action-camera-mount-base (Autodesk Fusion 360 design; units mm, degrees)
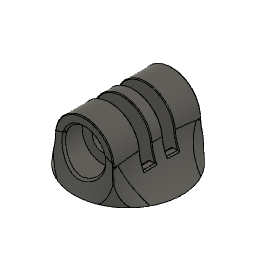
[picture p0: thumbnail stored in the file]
sketch "Sketch2" plane through (0, 0, 0) normal (1, 0, 0) x axis (0, 0, -1)
  line L1 (0, 60) -> (0, 0)
  line L2 (-14.75, 60) -> (0, 60)
  line L3 (-12.2, 0) -> (0, 0)
  line L4 (-12.2, 0) -> (-14.75, 60)
  point P1 (0, 0)
  point P2 (0, 0)
  point P5 (0, 0)
  point P3 (0, 60)
  point P6 (-12.2, 0)
  point P4 (-14.75, 60)
  coincident P1 P2
  vertical L1
  perpendicular L1 L2
  coincident P1 P5
  perpendicular L1 L3
  dimension "d4" distance P2 P3 = 60
  dimension "d7" distance P5 P6 = 12.2
  dimension "d8" distance P3 P4 = 14.75
revolve "Revolve1" sketch "Sketch2" AlongAngle 360
extrude "Extrude2" add of existing geometry blind 5
sketch "Sketch3" plane through (0, 0, 0) normal (1, 0, 0) x axis (0, 0, -1)
mesh "Mesh1"
extrude "Extrude3" add of existing geometry blind 1.394
chamfer "Chamfer1" distance 2.905
extrude "Extrude4" add of existing geometry blind 1.362
sketch "Sketch4" plane through (0, 0, 0) normal (1, 0, 0) x axis (0, 0, -1)
  line L1 (8, 77) -> (8, 67)
  line L2 (-8, 67) -> (-8, 77)
  line L3 (8, 67) -> (-8, 67)
  arc A1 centre (0, 77) radius 8 clockwise from (-8, 77) to (8, 77)
  circle C1 centre (0, 77) radius 2.75
  vertical L1
  vertical L2
  tangent L2 A1
  concentric A1 C1
  perpendicular L1 L3
  dimension "d18" diameter C1 = 5.5
extrude "Extrude5" new body sketch "Sketch4" along normal blind 8
extrude "Extrude6" cut of existing geometry blind -5
extrude "Extrude7" new body sketch "Sketch4" against normal blind 1.58
extrude "Extrude8" add sketch "Sketch4" along normal blind 1.58
extrude "Extrude9" add of existing geometry blind 17
extrude "Extrude10" add of existing geometry blind 0.18
extrude "Extrude11" cut of existing geometry blind -0.01
extrude "Extrude12" cut of existing geometry blind -0.01
move_face "MoveFace1"
extrude "Extrude13" add of existing geometry blind 6.41
extrude "Extrude14" cut of existing geometry blind -6.41
extrude "Extrude15" add sketch "Sketch4" against normal blind 1.58
extrude "Extrude16" add sketch "Sketch4" along normal blind 1.58
delete_face "DeleteFace1"
sketch "Sketch5" plane through (7.99, 0, 0) normal (1, 0, 0) x axis (0, 0, -1)
  line L1 (8, 67.756) -> (-8, 67.756)
  line L2 (8, 77) -> (8, 67.756)
  line L3 (-8, 67.756) -> (-8, 77)
  line L4 (0, 81.6188) -> (4, 79.3094)
  line L5 (-4, 79.3094) -> (0, 81.6188)
  line L6 (-4, 74.6906) -> (-4, 79.3094)
  line L7 (0, 72.3812) -> (-4, 74.6906)
  line L8 (4, 74.6906) -> (0, 72.3812)
  line L9 (4, 79.3094) -> (4, 74.6906)
  line L10 (-8, 69.1448) -> (-8, 77)
  line L11 (8, 69.1448) -> (-8, 69.1448)
  line L12 (8, 77) -> (8, 69.1448)
  arc A1 centre (0, 77) radius 8 clockwise from (-8, 77) to (8, 77)
  circle C1 centre (0, 77) radius 2.75
  arc A2 centre (0, 77) radius 8 clockwise from (-8, 77) to (8, 77)
  point P6 (0, 77)
  point P13 (0, 77)
  point P5 (-8, 77)
  point P18 (-8, 77)
  coincident P6 P13
  parallel L9 L10
  perpendicular L10 L11
  perpendicular L11 L12
  tangent L12 A2
  coincident P5 P18
extrude "Extrude17" add sketch "Sketch5" profile of L2 A1 L3 L4 L5 L6 L7 L8 L9 L10 L11 L12 along normal blind 4
extrude "Extrude18" add of existing geometry blind 2
chamfer "Chamfer2" distance 0.5
chamfer "Chamfer3" distance 2.75
fillet "Fillet1" radius 9
sketch "Sketch6" plane through (-7.99, 0, 0) normal (-1, 0, 0) x axis (0, 0, 1)
  line L1 (8, 67.756) -> (-8, 67.756)
  line L2 (8, 77) -> (8, 67.756)
  line L3 (-8, 67.756) -> (-8, 77)
  arc A1 centre (0, 77) radius 8 clockwise from (-8, 77) to (8, 77)
  circle C1 centre (0, 77) radius 2.75
  circle C2 centre (0, 77) radius 5.5
  concentric A1 C2
  dimension "d51" diameter C2 = 11
extrude "Extrude19" add sketch "Sketch6" profile of L1 L2 A1 L3 C2 along normal blind 4
chamfer "Chamfer4" distance 0.5
chamfer "Chamfer5" distance 2.7
fillet "Fillet2" radius 9
fillet "Fillet3" radius 9.5
fillet "Fillet4" radius 9.5
sketch "Sketch7" plane through (0, 0, 0) normal (0, 1, 0) x axis (1, 0, 0)
  circle C1 centre (0, 0) radius 15.5242
  point P1 (0, 0)
  point P2 (0, 0)
  coincident P1 P2
revolve "Revolve2" sketch "Sketch2" AlongAngle 360
extrude "Extrude21" add of existing geometry blind 7
extrude "Extrude22" add of existing geometry blind 1
extrude "Extrude23" add sketch "Sketch4" along normal blind 12
extrude "Extrude24" add sketch "Sketch4" against normal blind 12
fillet "Fillet5" radius 26
fillet "Fillet6" radius 26
fillet "Fillet7" radius 12
fillet "Fillet8" radius 12
sketch "Sketch8" plane through (-12, 0, 0) normal (-1, 0, 0) x axis (0, 0, 1)
  curve K1 (-7.9579, 77.8197) -> (-0.8377, 79.6193)
  curve K2 (0.8377, 79.6193) -> (7.9579, 77.8197)
  line L1 (0, 81.6188) -> (4, 79.3094)
  line L2 (-4, 79.3094) -> (0, 81.6188)
  line L3 (-4, 74.6906) -> (-4, 79.3094)
  line L4 (0, 72.3812) -> (-4, 74.6906)
  line L5 (4, 74.6906) -> (0, 72.3812)
  line L6 (4, 79.3094) -> (4, 74.6906)
  arc A1 centre (0, 77) radius 2.75 clockwise from (-0.8377, 79.6193) to (0.8377, 79.6193)
  arc A2 centre (0, 77) radius 8 clockwise from (-7.9579, 77.8197) to (7.9579, 77.8197)
  point P5 (0, 77)
  point P13 (0, 77)
  coincident P5 P13
extrude "Extrude25" cut sketch "Sketch8" profile of K1 A1 K2 L1 L2 L3 L4 L5 L6 along normal blind 3
extrude "Extrude26" cut sketch "Sketch8" profile of K1 A1 K2 L1 L2 L3 L4 L5 L6 against normal blind 4
chamfer "Chamfer6" distance 0.5
sketch "Sketch9" plane through (12, 0, 0) normal (1, 0, 0) x axis (0, 0, -1)
  curve K1 (-7.9579, 77.8197) -> (-0.8377, 79.6193)
  curve K2 (0.8377, 79.6193) -> (7.9579, 77.8197)
  arc A1 centre (0, 77) radius 2.75 clockwise from (-0.8377, 79.6193) to (0.8377, 79.6193)
  arc A2 centre (0, 77) radius 8 clockwise from (-7.9579, 77.8197) to (7.9579, 77.8197)
  circle C1 centre (0, 77) radius 5.5
  concentric A1 C1
  dimension "d86" diameter C1 = 11
extrude "Extrude27" cut sketch "Sketch9" profile of K1 A1 K2 C1 along normal blind 2
extrude "Extrude28" cut sketch "Sketch9" profile of K1 A1 K2 C1 against normal blind 4
chamfer "Chamfer7" distance 0.5
sketch "Sketch10" plane through (0, 0, 0) normal (0, 0, 1) x axis (1, 0, 0)
  line L1 (-1.58, 86) -> (0, 86)
  line L2 (-4.83, 86) -> (-1.58, 86)
  line L3 (1.58, 86) -> (0, 86)
  line L4 (4.83, 86) -> (1.58, 86)
  line L5 (7.99, 86) -> (4.83, 86)
  line L6 (-7.99, 86) -> (-4.83, 86)
  line L7 (1.58, 85) -> (4.83, 85)
  line L8 (1.58, 69) -> (1.58, 85)
  line L9 (4.83, 69) -> (1.58, 69)
  line L10 (4.83, 85) -> (4.83, 69)
  line L11 (-4.83, 85) -> (-1.58, 85)
  line L12 (-4.83, 69) -> (-4.83, 85)
  line L13 (-1.58, 69) -> (-4.83, 69)
  line L14 (-1.58, 85) -> (-1.58, 69)
  point P2 (0, 86)
  point P3 (-1.58, 86)
  point P4 (-4.83, 86)
  point P5 (1.58, 86)
  point P6 (4.83, 86)
  point P7 (7.99, 86)
  point P8 (-7.99, 86)
  horizontal L1
  parallel L1 L2
  parallel L1 L3
  parallel L3 L4
  parallel L4 L5
  parallel L2 L6
  horizontal L7
  vertical L8
  horizontal L9
  vertical L10
  horizontal L11
  vertical L12
  horizontal L13
  vertical L14
  dimension "d92" distance P2 P3 = 1.58
  dimension "d93" distance P3 P4 = 3.25
  dimension "d94" distance P2 P5 = 1.58
  dimension "d95" distance P5 P6 = 3.25
  dimension "d96" distance P6 P7 = 3.16
  dimension "d97" distance P4 P8 = 3.16
extrude "Extrude40" new body sketch "Sketch10" profile of L7 L8 L9 L10 L11 L12 L13 L14 along normal blind 8.1
extrude "Extrude41" add of existing geometry blind 8.1
extrude "Extrude42" add of existing geometry blind 0.2
sketch "Sketch14" plane through (-4.83, 0, 0) normal (-1, 0, 0) x axis (0, 0, 1)
  line L1 (-8.1, 76.9) -> (-8.1, 85)
  line L2 (8.1, 85) -> (-8.1, 85)
  line L3 (8.1, 76.9) -> (8.1, 85)
  arc A1 centre (0, 76.9) radius 8.1 clockwise from (8.1, 76.9) to (-8.1, 76.9)
  point P2 (-8.1, 85)
  point P3 (-8.1, 76.9)
  point P4 (8.1, 85)
  point P5 (8.1, 76.9)
  vertical L1
  perpendicular L1 L2
  perpendicular L2 L3
  tangent L1 A1
  dimension "d149" distance P2 P3 = 8.1
  dimension "d151" distance P4 P5 = 8.1
extrude "Extrude43" cut sketch "Sketch14" against normal blind 1
extrude "Extrude44" cut of existing geometry blind -10
extrude "Extrude45" add of existing geometry blind 1
combine "Combine4"
combine "Combine5"
chamfer "Chamfer9" distance 3.5
fillet "Fillet12" radius 0.5
fillet "Fillet13" radius 0.2
copy_paste_bodies "CopyPasteBodies3"
sketch "Sketch15" plane through (0, 0, 0) normal (0, 1, 0) x axis (1, 0, 0)
  circle C1 centre (0, 0) radius 15
  point P1 (0, 0)
  point P2 (0, 0)
  coincident P1 P2
extrude "Extrude46" cut sketch "Sketch15" along normal blind 30
move "Move2"
extrude "Extrude47" cut of existing geometry blind -1
extrude "Extrude48" cut of existing geometry blind -1
copy_paste_bodies "CopyPasteBodies4"
extrude "Extrude49" cut sketch "Sketch15" along normal blind 38
move "Move3"
move_face "MoveFace2"
move_face "MoveFace3"
move_face "MoveFace4"
move_face "MoveFace5"
move_face "MoveFace6"
move_face "MoveFace7"
move_face "MoveFace8"
move "Move4"
fillet "Fillet14" radius 0.2
sketch "Sketch16" plane through (0, 0, 0) normal (0, 1, 0) x axis (1, 0, 0)
  circle C1 centre (0, 0) radius 2.5
  point P1 (0, 0)
  point P2 (0, 0)
  coincident P1 P2
align "Align1"
extrude "Extrude29" new body sketch "Sketch10" along normal blind 8
extrude "Extrude30" add of existing geometry blind 8
extrude "Extrude31" add of existing geometry blind 0.2
extrude "Extrude32" add of existing geometry blind 0.1
extrude "Extrude33" add of existing geometry blind 0.1
sketch "Sketch11" plane through (-7.99, 0, 0) normal (-1, 0, 0) x axis (0, 0, 1)
  line L1 (-8.1, 85) -> (8.1, 85)
  line L2 (-8.1, 68.8) -> (-8.1, 85)
  line L3 (8.1, 68.8) -> (-8.1, 68.8)
  line L4 (8.1, 85) -> (8.1, 68.8)
  line L5 (-8.1, 76.9) -> (-8.1, 85)
  line L6 (8.1, 85) -> (-8.1, 85)
  line L7 (8.1, 76.9) -> (8.1, 85)
  arc A1 centre (0, 76.9) radius 8.1 clockwise from (8.1, 76.9) to (-8.1, 76.9)
  point P3 (-8.1, 85)
  point P6 (-8.1, 85)
  point P8 (-8.1, 85)
  point P2 (8.1, 85)
  point P9 (8.1, 85)
  point P10 (8.1, 85)
  point P7 (-8.1, 76.9)
  point P11 (8.1, 76.9)
  coincident P3 P6
  perpendicular L1 L5
  coincident P3 P8
  coincident P2 P9
  coincident P2 P10
  tangent L7 A1
  dimension "d119" distance P6 P7 = 8.1
  dimension "d120" angle L6 L7 = 90
  dimension "d121" distance P10 P11 = 8.1
extrude "Extrude34" cut sketch "Sketch11" profile of L2 L3 L4 A1 against normal blind 17
combine "Combine1"
combine "Combine2"
combine "Combine3"
chamfer "Chamfer8" distance 3.5
fillet "Fillet9" radius 0.5
fillet "Fillet10" radius 0.2
fillet "Fillet11" radius 0.2
extrude "Extrude35" add of existing geometry blind 1.5
extrude "Extrude36" add of existing geometry blind 1.5
extrude "Extrude37" add of existing geometry blind 0.5
extrude "Extrude38" add of existing geometry blind 0.5
sketch "Sketch12" plane through (0, 0, 0) normal (0, 1, 0) x axis (1, 0, 0)
  circle C1 centre (0, 0) radius 15
  point P1 (0, 0)
  point P2 (0, 0)
  coincident P1 P2
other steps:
base_feature "Base Feature3" bodies "V4", "V4 - small"
base_feature "Base Feature4" bodies "V4 - small", "V4 - small (1)"
named bodies: "V3", "V4", "V4 - small", "V4 - small (1)"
